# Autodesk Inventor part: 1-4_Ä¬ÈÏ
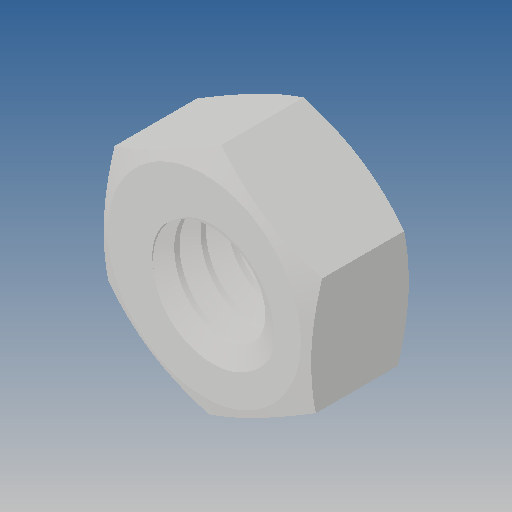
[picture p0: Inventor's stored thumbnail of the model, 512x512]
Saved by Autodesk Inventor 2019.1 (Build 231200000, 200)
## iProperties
Created: 2010-06
Part Number: 1-4_Ä¬ÈÏ
Material: Ogólny
Document SubType Name: Modeling
Designer: CADENGINEERING4
Density: 1 g/cm^3
Appearance: Domyślna
Author: CADENGINEERING4
Revision Number: ÈÎºÎ
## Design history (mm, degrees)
feature "NONE"
node "Bryła1"
